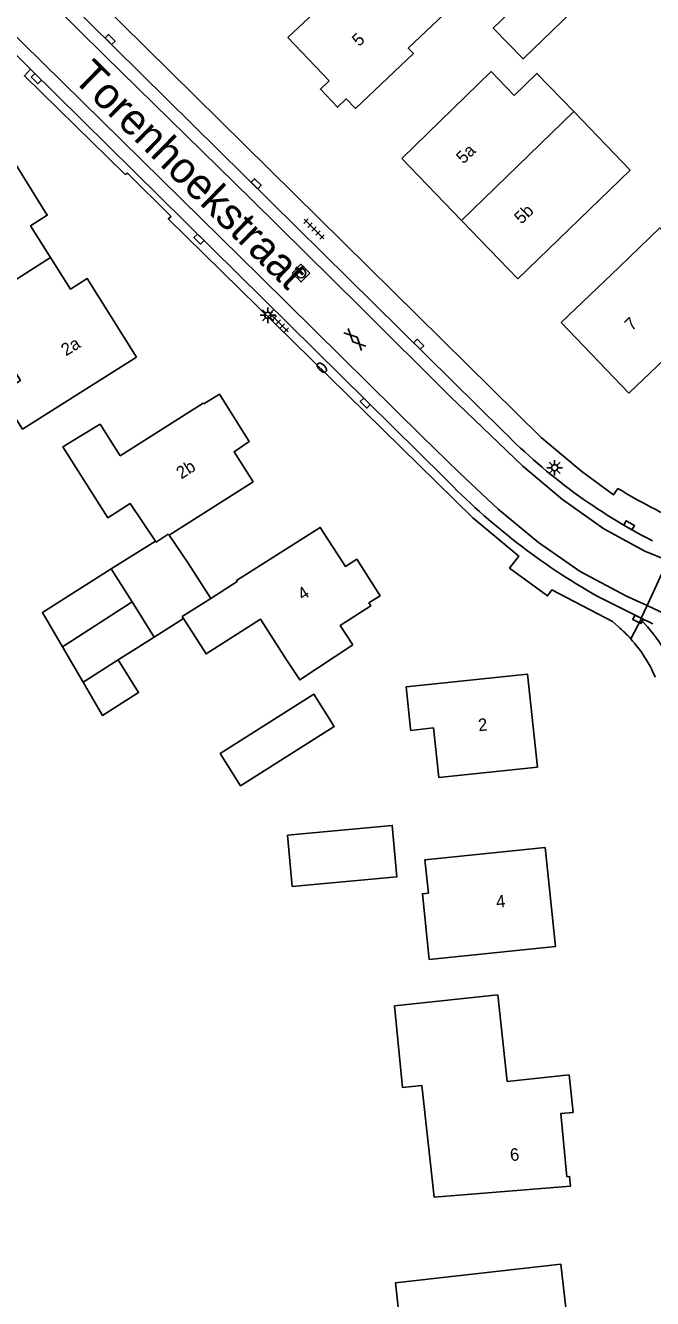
# Model space of a CAD drawing. Extents: x 136000 to 138005, y 398500 to 400500.
# Drawn here: x 137708.8 to 137759.2, y 398873.8 to 398976.2 of the extents above; entities that cross this region are included whole.
import ezdxf

# ---------------------------------------------------------------- set-up
doc = ezdxf.new("R2010")
doc.units = 0
for name, color, linetype in [('gg-anno-huisnummerreeks BGT', 7, 'Continuous'), ('gg-anno-openbare ruimte label', 7, 'Continuous'), ('gg-bbg-gedigitaliseerde bebouwing', 7, 'Continuous'), ('gg-bbg-gedigitaliseerde bijgebouw', 7, 'Continuous'), ('gg-bbg-hoofdgebouw', 7, 'Continuous'), ('gg-bbg-luifel en loopbrug', 7, 'Continuous'), ('gg-bbg-tussenscheiding', 7, 'Continuous'), ('gg-knt-verharding', 7, 'Continuous'), ('gg-knt-verharding nz', 7, 'Continuous'), ('gt-grn-weggrens', 7, 'Continuous'), ('gt-symb-brandkraan', 7, 'Continuous'), ('gt-symb-gesloten verharding', 7, 'Continuous'), ('gt-symb-kolk', 7, 'Continuous'), ('gt-symb-lichtmast', 7, 'Continuous'), ('gt-symb-rioolschacht', 7, 'Continuous'), ('gt-symb-tegel verharding', 7, 'Continuous')]:
    doc.layers.add(name, color=color, linetype=linetype)

# ---------------------------------------------------------------- blocks, each defined once
blk = doc.blocks.new('gt0-KOLK')
at = {"layer": 'gt-symb-kolk'}
blk.add_lwpolyline([(0, 0), (0.37, 0), (0.37, 0.4), (-0.38, 0.4), (-0.38, 0), (0, 0)], dxfattribs=at)
blk = doc.blocks.new('gt0-GESVH1')
at = {"layer": 'gt-symb-gesloten verharding'}
for p, q in [((-0.99, -0.26), (0.01, 0.24)), ((0.01, -0.26), (-0.99, 0.24)), ((0.01, 0.24), (1.01, -0.26)), ((1.01, 0.24), (0.01, -0.26))]:
    blk.add_line(p, q, dxfattribs=at)
blk = doc.blocks.new('gt0-LMAST')
at = {"layer": 'gt-symb-lichtmast'}
for p, q in [((-0.18, 0.17), (-0.45, 0.44)), ((-0.01, 0.25), (-0.01, 0.62)), ((0.17, 0.17), (0.44, 0.44)), ((-0.26, 0), (-0.63, 0)), ((-0.18, -0.18), (-0.45, -0.45)), ((-0.01, -0.25), (-0.01, -0.63)), ((0.44, -0.45), (0.17, -0.18)), ((0.24, 0), (0.62, 0))]:
    blk.add_line(p, q, dxfattribs=at)
blk.add_circle((-0.01, 0), 0.25, dxfattribs=at)
blk = doc.blocks.new('gt0-TEG1')
at = {"layer": 'gt-symb-tegel verharding'}
for p, q in [((-1.12, 0), (1.12, 0)), ((-0.9, -0.25), (-0.9, 0.25)), ((-0.45, -0.25), (-0.45, 0.25)), ((0, -0.25), (0, 0.25)), ((0.45, -0.25), (0.45, 0.25)), ((0.9, -0.25), (0.9, 0.25))]:
    blk.add_line(p, q, dxfattribs=at)
blk = doc.blocks.new('gt0-RS')
at = {"layer": 'gt-symb-rioolschacht'}
blk.add_lwpolyline([(-0.5, -0.5), (0.5, -0.5), (0.5, 0.5), (-0.5, 0.5)], close=True, dxfattribs=at)
blk.add_circle((0, 0), 0.375, dxfattribs=at)
blk = doc.blocks.new('gt0-BR')
at = {"layer": 'gt-symb-brandkraan'}
for centre, radius, start, end in [((-0.24, 0), 0.206, 107.5669, 252.4331), ((0.6, -2.66), 3, 106.892, 107.5669), ((0, -0.69), 0.938, 73.108, 106.892), ((-0.6, -2.66), 3, 72.4331, 73.108), ((0.24, 0), 0.206, 287.567, 72.4331), ((0.6, 2.66), 3, 252.4331, 253.108), ((0, 0.69), 0.938, 253.108, 286.8921), ((-0.6, 2.66), 3, 286.8921, 287.567)]:
    blk.add_arc(centre, radius, start, end, dxfattribs=at)

msp = doc.modelspace()

# ---------------------------------------------------------------- linework, layer by layer
at = {"layer": 'gg-bbg-gedigitaliseerde bebouwing'}
for p, q in [((137752.89, 398969.27), (137757.42, 398964.55)), ((137751.85, 398952.3), (137756.52, 398956.76)), ((137720.31, 398935.19), (137727.07, 398939.48)), ((137746.77, 398898.22), (137738.45, 398897.35))]:
    msp.add_line(p, q, dxfattribs=at)
for points in [[(137729.88, 398975.22), (137734.54, 398979.63), (137735.1, 398979.04), (137738.3, 398982.07)], [(137739.03, 398965.5), (137746.23, 398972.48), (137748.07, 398970.56)], [(137752.89, 398969.27), (137749.91, 398972.34), (137748.07, 398970.56)], [(137756.52, 398956.76), (137759.81, 398959.91), (137762.38, 398957.22)], [(137706.23, 398950.99), (137708.35, 398947.64), (137706.7, 398946.6), (137708.52, 398943.73), (137711.67, 398945.72)], [(137713.21, 398943.18), (137711.77, 398942.3), (137715.38, 398936.6), (137717.18, 398937.74), (137719.23, 398934.73)], [(137719.23, 398934.73), (137719.28, 398934.65), (137720.25, 398935.27), (137720.31, 398935.19)], [(137723.66, 398930.11), (137721.37, 398928.65), (137721.46, 398928.5)], [(137721.46, 398928.5), (137723.29, 398925.65), (137727.66, 398928.45), (137729.76, 398925.17)], [(137735.11, 398926.38), (137730.82, 398923.56), (137729.76, 398925.17)], [(137739.75, 398919.62), (137739.76, 398919.5), (137741.59, 398919.7), (137742.02, 398915.7), (137749.95, 398916.55)], [(137751.4, 398902.12), (137741.25, 398901.06), (137740.7, 398906.36), (137741.18, 398906.41), (137740.9, 398909.08), (137750.58, 398910.09)], [(137738.45, 398897.35), (137739.08, 398890.78), (137740.66, 398890.93), (137741.64, 398881.96), (137752.61, 398882.84)], [(137751.83, 398876.57), (137738.54, 398875.07), (137738.99, 398870.91), (137741.42, 398871.17)]]:
    msp.add_lwpolyline(points, dxfattribs=at)
at = {"layer": 'gg-bbg-gedigitaliseerde bijgebouw'}
for p, q in [((137717.33, 398929.83), (137715.66, 398932.48)), ((137717.33, 398929.83), (137719.12, 398927)), ((137716.21, 398925.16), (137719.12, 398927)), ((137711.74, 398926.21), (137713.39, 398923.38)), ((137713.39, 398923.38), (137716.21, 398925.16))]:
    msp.add_line(p, q, dxfattribs=at)
for points in [[(137750.99, 398980.44), (137746.39, 398975.98), (137748.8, 398973.5), (137753.51, 398978.07)], [(137715.66, 398932.48), (137710.12, 398928.98), (137711.74, 398926.21)], [(137724.41, 398917.63), (137726.05, 398915.05), (137733.6, 398919.82), (137731.97, 398922.4), (137724.41, 398917.63)], [(137729.84, 398911.08), (137730.22, 398906.95), (137738.65, 398907.72), (137738.27, 398911.85), (137729.84, 398911.08)]]:
    msp.add_lwpolyline(points, dxfattribs=at)
at = {"layer": 'gg-bbg-hoofdgebouw'}
for p, q in [((137733.19, 398971.74), (137729.88, 398975.22)), ((137743.85, 398960.51), (137739.03, 398965.5)), ((137748.36, 398955.83), (137757.42, 398964.55)), ((137748.36, 398955.83), (137743.85, 398960.51)), ((137757.29, 398946.62), (137751.85, 398952.3)), ((137717.7, 398949.52), (137711.67, 398945.72)), ((137713.21, 398943.18), (137714.77, 398944.12)), ((137750.58, 398910.09), (137751.4, 398902.12)), ((137752.31, 398872.36), (137751.83, 398876.57))]:
    msp.add_line(p, q, dxfattribs=at)
for points in [[(137746.73, 398981.17), (137739.55, 398974.37), (137739.97, 398973.93), (137735.31, 398969.51)], [(137735.31, 398969.51), (137734.55, 398970.29), (137733.87, 398969.62), (137732.49, 398971.07), (137733.19, 398971.74)], [(137710.78, 398957.54), (137709.17, 398960.08), (137710.51, 398960.93), (137706.55, 398967.26)], [(137717.7, 398949.52), (137713.72, 398955.85), (137712.39, 398954.99), (137710.78, 398957.54)], [(137764.42, 398954.2), (137761.49, 398951.41), (137761.88, 398951), (137757.29, 398946.62)], [(137727.07, 398939.48), (137725.54, 398941.91), (137726.77, 398942.74), (137724.36, 398946.54), (137723.1, 398945.75)], [(137723.1, 398945.75), (137723.05, 398945.82), (137716.38, 398941.59), (137714.77, 398944.12)], [(137723.66, 398930.11), (137725.79, 398931.47), (137725.74, 398931.55), (137732.48, 398935.82), (137734.5, 398932.68), (137735.41, 398933.27), (137737.29, 398930.33), (137736.39, 398929.75), (137736.54, 398929.51), (137734.09, 398927.93), (137735.11, 398926.38)], [(137749.95, 398916.55), (137749.15, 398924.03), (137739.4, 398922.99), (137739.75, 398919.62)], [(137746.77, 398898.22), (137747.51, 398891.27), (137752.5, 398891.8)], [(137752.61, 398882.84), (137752.54, 398883.62), (137752.32, 398883.59), (137751.82, 398888.68), (137752.82, 398888.77), (137752.5, 398891.8)]]:
    msp.add_lwpolyline(points, dxfattribs=at)
at = {"layer": 'gg-bbg-luifel en loopbrug'}
for p, q in [((137721.85, 398932.95), (137720.31, 398935.19)), ((137719.23, 398934.73), (137715.66, 398932.48)), ((137723.66, 398930.11), (137721.85, 398932.95)), ((137719.12, 398927), (137721.46, 398928.5))]:
    msp.add_line(p, q, dxfattribs=at)
msp.add_lwpolyline([(137713.39, 398923.38), (137714.95, 398920.7), (137717.86, 398922.54), (137716.21, 398925.16)], dxfattribs=at)
at = {"layer": 'gg-bbg-tussenscheiding'}
for p, q in [((137743.85, 398960.51), (137752.89, 398969.27)), ((137704.59, 398953.58), (137710.78, 398957.54)), ((137717.33, 398929.83), (137711.74, 398926.21))]:
    msp.add_line(p, q, dxfattribs=at)
at = {"layer": 'gg-knt-verharding'}
for p, q in [((137707.25, 398983.01), (137747.25, 398943.51)), ((137709.16, 398972.68), (137705.21, 398976.57)), ((137709.16, 398972.68), (137742.47, 398939.82)), ((137754.76, 398930.29), (137758.3, 398928.52)), ((137755.99, 398928.25), (137756.45, 398927.85)), ((137758.26, 398928.38), (137758.3, 398928.52)), ((137758.3, 398928.52), (137759.23, 398928.07))]:
    msp.add_line(p, q, dxfattribs=at)
for points in [[(137756.43, 398938.95), (137756.06, 398938.44), (137753.53, 398940.31), (137750.24, 398943.05), (137708.49, 398984.27)], [(137709.16, 398972.68), (137708.67, 398972.14), (137716.78, 398964.22), (137716.97, 398964.31), (137720.47, 398960.84), (137720.25, 398960.63), (137744.75, 398936.59), (137748.44, 398933.52), (137747.71, 398932.55), (137750.76, 398930.31), (137751.11, 398930.81), (137755.99, 398928.25)]]:
    msp.add_lwpolyline(points, dxfattribs=at)
for centre, radius, start, end in [((137780.36, 398976.12), 46.47, 224.5696, 242.9302), ((137781.26, 398977.16), 53.84, 223.912, 240.5158), ((137781.8, 398980.72), 48.87, 238.7254, 245.8489), ((137751.82, 398921.46), 9.45, 9.6857, 47.0657), ((137749.06, 398919.26), 11.33, 42.1226, 49.2565), ((137749.15, 398919.36), 11.19, 23.2121, 42.0611)]:
    msp.add_arc(centre, radius, start, end, dxfattribs=at)
at = {"layer": 'gg-knt-verharding nz'}
for points in [[(137706.51, 398982.27), (137715.15, 398973.74), (137726.91, 398962.22), (137735.69, 398953.56), (137742.93, 398946.34), (137748.77, 398940.74), (137751.96, 398938.08), (137755.28, 398935.71), (137758.58, 398933.92), (137760.44, 398933.15)], [(137703.73, 398979.52), (137727.68, 398955.98), (137740.65, 398943.15), (137743.7, 398940.18), (137746.8, 398937.3), (137750.03, 398934.61), (137753.38, 398932.28), (137757.11, 398930.29), (137758.77, 398929.53)], [(137758.77, 398929.53), (137760.86, 398928.56), (137765.03, 398927.31), (137769.63, 398926.3), (137777.29, 398925.11), (137781.47, 398924.54), (137829.3, 398917.72)]]:
    msp.add_lwpolyline(points, dxfattribs=at)
at = {"layer": 'gt-grn-weggrens'}
for p, q in [((137758.77, 398929.53), (137760.44, 398933.15)), ((137758.3, 398928.52), (137758.77, 398929.53)), ((137757.46, 398926.86), (137758.26, 398928.38))]:
    msp.add_line(p, q, dxfattribs=at)

# ---------------------------------------------------------------- block references
at = {"layer": 'gt-symb-brandkraan', "rotation": -44.59480322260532}
msp.add_blockref('gt0-BR', (137732.61, 398948.67), dxfattribs=at)
at = {"layer": 'gt-symb-gesloten verharding', "rotation": -44.635579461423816}
msp.add_blockref('gt0-GESVH1', (137735.26, 398950.95), dxfattribs=at)
at = {"layer": 'gt-symb-kolk'}
for p, rotation in [((137715.43, 398974.92), -44.635579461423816), ((137709.5, 398971.77), -44.63557946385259), ((137727.18, 398963.32), -44.635579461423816), ((137722.58, 398958.87), -44.63557946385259), ((137740.26, 398950.41), -44.635579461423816), ((137735.96, 398945.68), -44.635579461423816), ((137757.23, 398935.82), -30.000727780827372), ((137757.96, 398928.25), -26.488178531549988)]:
    msp.add_blockref('gt0-KOLK', p, dxfattribs=dict(at, rotation=rotation))
at = {"layer": 'gt-symb-lichtmast'}
for p in [(137728.27, 398952.89), (137751.34, 398940.62)]:
    msp.add_blockref('gt0-LMAST', p, dxfattribs=at)
at = {"layer": 'gt-symb-rioolschacht', "rotation": -44.635579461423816}
msp.add_blockref('gt0-RS', (137730.93, 398956.28), dxfattribs=at)
at = {"layer": 'gt-symb-tegel verharding', "rotation": -44.635579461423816}
for p in [(137731.97, 398959.82), (137729.1, 398952.34)]:
    msp.add_blockref('gt0-TEG1', p, dxfattribs=at)

# ---------------------------------------------------------------- texts
at = {"layer": 'gg-anno-huisnummerreeks BGT'}
for s, rotation, p in [('5', 43.5, (137735.6, 398974.45)), ('5a', 43.9, (137743.99, 398965.01)), ('5b', 43.9, (137748.66, 398960.16)), ('7', 43.8, (137757.54, 398951.58)), ('2a', 32.1, (137712.02, 398949.57)), ('2b', 32.4, (137721.29, 398939.67)), ('4', 32.8, (137731.06, 398929.92)), ('2', 6.1, (137745.23, 398919.42)), ('4', 5.9, (137746.67, 398905.22)), ('6', 5.6, (137747.79, 398884.85))]:
    msp.add_text(s, height=1, rotation=rotation, dxfattribs=at).set_placement(p)
at = {"layer": 'gg-anno-openbare ruimte label'}
msp.add_text('Torenhoekstraat', height=2.5, rotation=315.6, dxfattribs=at).set_placement((137712.48, 398971.86))

doc.saveas('drawing.dxf')
